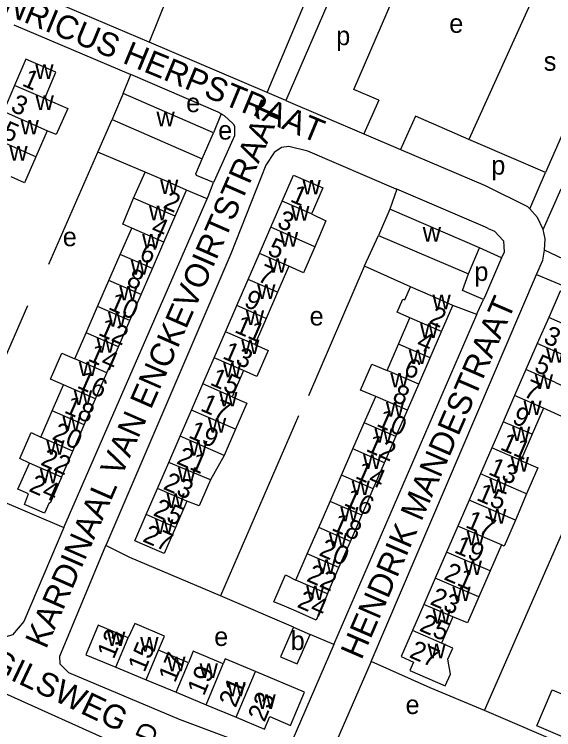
# Model space of a CAD drawing. Extents: x 162804 to 165059, y 381530 to 382901.
# Drawn here: x 163529.9 to 163644.1, y 381809.3 to 381960.8 of the extents above; entities that cross this region are included whole.
import ezdxf

# ---------------------------------------------------------------- set-up
doc = ezdxf.new("R2010")
doc.units = 0
for name, color, linetype in [('BLT_Basislijn', 7, 'Continuous'), ('BLT_Bebouwing', 7, 'Continuous'), ('BLT_Centroide', 7, 'Continuous'), ('BLT_Huisnummer', 7, 'Continuous'), ('BLT_Huisnummer_ tussenligend', 7, 'Continuous'), ('BLT_Onderverdeling_panden', 7, 'Continuous'), ('BLT_Straatnaam', 7, 'Continuous'), ('BLT_Straatnaam_verkleind', 7, 'Continuous')]:
    doc.layers.add(name, color=color, linetype=linetype)

msp = doc.modelspace()

# ---------------------------------------------------------------- linework, layer by layer
at = {"layer": 'BLT_Basislijn'}
for p, q in [((163583.47, 381944.21), (163604.25, 381993.64)), ((163564.81, 381970.7), (163558.49, 381954.86)), ((163643.05, 381971.55), (163626.16, 381934.28)), ((163529.87, 381958.54), (163554.61, 381948.03)), ((163583.47, 381944.21), (163558.49, 381954.86)), ((163553, 381943.96), (163554.61, 381948.03)), ((163650.53, 381946.02), (163642.4, 381927.25)), ((163587.41, 381942.48), (163583.47, 381944.21)), ((163587.41, 381942.48), (163603.92, 381935.46)), ((163607.08, 381942.55), (163603.92, 381935.46)), ((163573.75, 381939.66), (163572.1, 381935.63)), ((163614.86, 381939.18), (163611.68, 381932.16)), ((163622.11, 381936.04), (163614.86, 381939.18)), ((163547.65, 381931.6), (163550.62, 381938.48)), ((163626.16, 381934.28), (163622.11, 381936.04)), ((163603.92, 381935.46), (163611.68, 381932.16)), ((163637.17, 381929.52), (163626.16, 381934.28)), ((163537.22, 381907.84), (163547.65, 381931.6)), ((163557.61, 381927.35), (163547.65, 381931.6)), ((163642.4, 381927.25), (163637.17, 381929.52)), ((163639.05, 381919.56), (163642.4, 381927.25)), ((163570.74, 381921.68), (163566.39, 381923.52)), ((163610.9, 381923.7), (163609.39, 381919.47)), ((163641.88, 381915.19), (163645.68, 381923.83)), ((163540.41, 381852.1), (163570.74, 381921.68)), ((163633.08, 381909.22), (163628.42, 381911.3)), ((163592.25, 381880.07), (163604.04, 381907.4)), ((163613.77, 381903.03), (163604.04, 381907.4)), ((163605.48, 381823.75), (163640.46, 381905.63)), ((163640.46, 381905.63), (163646.54, 381903.09)), ((163532.73, 381899.02), (163516.61, 381862.19)), ((163627.8, 381897.16), (163622.78, 381899.11)), ((163597.55, 381827.29), (163627.8, 381897.16)), ((163629.47, 381813.33), (163659.78, 381882.71)), ((163590.12, 381875.77), (163573.56, 381837.61)), ((163516.61, 381862.19), (163540.41, 381852.1)), ((163589.02, 381830.96), (163573.56, 381837.61)), ((163597.55, 381827.29), (163592.54, 381829.44)), ((163553.38, 381805.49), (163514.14, 381823.1)), ((163653.55, 381803.05), (163629.47, 381813.33))]:
    msp.add_line(p, q, dxfattribs=at)
for points in [[(163558.49, 381954.86), (163523.49, 381969.76), (163513.52, 381972.17), (163497.69, 381979.1), (163495.7, 381979.97)], [(163610.67, 381965.27), (163599.23, 381969.98), (163587.41, 381942.48)], [(163607.08, 381942.55), (163601.81, 381944.83), (163609.95, 381963.6)], [(163573.75, 381939.66), (163573.06, 381940), (163554.61, 381948.03)], [(163573.75, 381939.66), (163574.39, 381939.33), (163576.23, 381937.58), (163576.53, 381937.09), (163576.58, 381935.04), (163572.49, 381926.04), (163572.13, 381925.13)], [(163610.9, 381923.7), (163610.79, 381923.74), (163592.09, 381931.76), (163588.05, 381932.8), (163586.48, 381932.52), (163584.92, 381931.48), (163583.18, 381928.83), (163575.79, 381910.04), (163549.28, 381848.27)], [(163611.68, 381932.16), (163629.61, 381924.53), (163638.58, 381920.07)], [(163572.13, 381925.13), (163568.51, 381926.63), (163568.35, 381926.96), (163569.71, 381930.16)], [(163570.74, 381921.68), (163570.96, 381922.2), (163572.13, 381925.13)], [(163630.26, 381915.42), (163629.69, 381915.67), (163610.9, 381923.7)], [(163639.05, 381919.56), (163638.58, 381920.07)], [(163641.88, 381915.19), (163640.71, 381917.75), (163639.05, 381919.56)], [(163630.26, 381915.42), (163631.54, 381914.84), (163633.47, 381912.77), (163633.6, 381910.42), (163633.08, 381909.22)], [(163642.18, 381910.81), (163642.27, 381913.24), (163641.88, 381915.19)], [(163604.04, 381907.4), (163604.09, 381907.52), (163607.02, 381913.95)], [(163640.46, 381905.63), (163641.77, 381908.72), (163642.18, 381910.81)], [(163690.48, 381889.85), (163648.86, 381907.67), (163642.18, 381910.81)], [(163633.08, 381909.22), (163629.65, 381901.31), (163629.24, 381900.39)], [(163629.24, 381900.39), (163624.78, 381902.26), (163626.05, 381905.77)], [(163627.8, 381897.16), (163628.01, 381897.63), (163629.24, 381900.39)], [(163540.41, 381852.1), (163531.99, 381832.17), (163529.54, 381829.36), (163528.01, 381828.87), (163525.62, 381828.73), (163483.29, 381849.03)], [(163597.55, 381827.29), (163588.69, 381806.75), (163587.02, 381805), (163585.93, 381804.58), (163583.75, 381804.36), (163564.87, 381811.42), (163541.46, 381821.29), (163539.68, 381823.17), (163539.55, 381824.83), (163549.28, 381848.27)], [(163573.56, 381837.61), (163554.4, 381845.76), (163549.28, 381848.27)], [(163605.48, 381823.75), (163598.15, 381806.85), (163597.24, 381803.85), (163596.76, 381800.38), (163598.72, 381798.05), (163642.29, 381783.55), (163644.18, 381783.63), (163645.81, 381785.02), (163653.55, 381803.05)], [(163629.47, 381813.33), (163617.95, 381818.13), (163605.48, 381823.75)]]:
    msp.add_lwpolyline(points, dxfattribs=at)
at = {"layer": 'BLT_Bebouwing'}
for p, q in [((163530.01, 381945.7), (163527.63, 381940.17)), ((163572.1, 381935.63), (163553, 381943.96)), ((163550.62, 381938.48), (163569.71, 381930.16)), ((163536.91, 381936.11), (163534.51, 381930.59)), ((163569.71, 381930.16), (163572.1, 381935.63)), ((163555.2, 381921.83), (163557.61, 381927.35)), ((163563.99, 381918), (163566.39, 381923.52)), ((163584.23, 381915.67), (163586.63, 381921.21)), ((163609.39, 381919.47), (163607.02, 381913.95)), ((163628.42, 381911.3), (163609.39, 381919.47)), ((163561.58, 381912.48), (163563.99, 381918)), ((163552.38, 381909.91), (163554.78, 381915.44)), ((163581.83, 381910.14), (163584.23, 381915.67)), ((163607.02, 381913.95), (163626.05, 381905.77)), ((163559.17, 381906.95), (163561.58, 381912.48)), ((163626.05, 381905.77), (163628.42, 381911.3)), ((163549.97, 381904.39), (163552.38, 381909.91)), ((163579.43, 381904.61), (163581.83, 381910.14)), ((163556.77, 381901.43), (163559.17, 381906.95)), ((163588.04, 381907.45), (163585.64, 381901.91)), ((163547.56, 381898.86), (163549.97, 381904.39)), ((163577.03, 381899.08), (163579.43, 381904.61)), ((163554.36, 381895.9), (163556.77, 381901.43)), ((163585.64, 381901.91), (163583.24, 381896.38)), ((163545.16, 381893.34), (163547.56, 381898.86)), ((163574.63, 381893.54), (163577.03, 381899.08)), ((163620.37, 381893.57), (163622.78, 381899.11)), ((163583.24, 381896.38), (163580.85, 381890.85)), ((163611.26, 381890.93), (163613.67, 381896.48)), ((163643.04, 381896.58), (163640.64, 381891.06)), ((163551.96, 381890.38), (163554.36, 381895.9)), ((163542.75, 381887.81), (163545.16, 381893.34)), ((163572.23, 381888.01), (163574.63, 381893.54)), ((163617.96, 381888.01), (163620.37, 381893.57)), ((163549.55, 381884.85), (163551.96, 381890.38)), ((163608.84, 381885.37), (163611.26, 381890.93)), ((163640.64, 381891.06), (163638.24, 381885.53)), ((163569.83, 381882.48), (163572.23, 381888.01)), ((163615.54, 381882.46), (163617.96, 381888.01)), ((163638.24, 381885.53), (163635.83, 381880.01)), ((163547.14, 381879.33), (163549.55, 381884.85)), ((163578.45, 381885.32), (163576.05, 381879.79)), ((163537.94, 381876.76), (163540.35, 381882.29)), ((163567.43, 381876.95), (163569.83, 381882.48)), ((163613.13, 381876.91), (163615.54, 381882.46)), ((163604.02, 381874.27), (163606.43, 381879.82)), ((163635.83, 381880.01), (163633.43, 381874.48)), ((163544.74, 381873.8), (163547.14, 381879.33)), ((163535.53, 381871.24), (163537.94, 381876.76)), ((163565.04, 381871.42), (163567.43, 381876.95)), ((163610.72, 381871.36), (163613.13, 381876.91)), ((163641.95, 381877.35), (163639.55, 381871.82)), ((163542.33, 381868.28), (163544.74, 381873.8)), ((163601.6, 381868.72), (163604.02, 381874.27)), ((163633.43, 381874.48), (163631.02, 381868.96)), ((163576.79, 381872.94), (163574.37, 381867.36)), ((163562.64, 381865.88), (163565.04, 381871.42)), ((163608.3, 381865.81), (163610.72, 381871.36)), ((163639.55, 381871.82), (163637.15, 381866.29)), ((163631.02, 381868.96), (163628.62, 381863.43)), ((163539.93, 381862.75), (163542.33, 381868.28)), ((163574.37, 381867.36), (163571.45, 381862.16)), ((163599.19, 381863.17), (163601.6, 381868.72)), ((163560.24, 381860.35), (163562.64, 381865.88)), ((163605.89, 381860.25), (163608.3, 381865.81)), ((163596.78, 381857.61), (163599.19, 381863.17)), ((163628.62, 381863.43), (163626.22, 381857.9)), ((163557.84, 381854.82), (163560.24, 381860.35)), ((163603.48, 381854.7), (163605.89, 381860.25)), ((163638.38, 381859.19), (163636.02, 381853.66)), ((163566.45, 381857.66), (163564.05, 381852.12)), ((163594.36, 381852.06), (163596.78, 381857.61)), ((163626.22, 381857.9), (163623.81, 381852.38)), ((163601.07, 381849.15), (163603.48, 381854.7)), ((163623.81, 381852.38), (163621.41, 381846.85)), ((163591.95, 381846.51), (163594.36, 381852.06)), ((163598.65, 381843.6), (163601.07, 381849.15)), ((163633.07, 381848.4), (163630.68, 381842.89)), ((163589.54, 381840.96), (163591.95, 381846.51)), ((163621.41, 381846.85), (163619.01, 381841.33)), ((163596.24, 381838.05), (163598.65, 381843.6)), ((163630.68, 381842.89), (163628.29, 381837.39)), ((163619.01, 381841.33), (163616.6, 381835.8)), ((163616.6, 381835.8), (163614.2, 381830.28)), ((163622.73, 381833.14), (163620.33, 381827.61)), ((163589.02, 381830.96), (163586.31, 381824.74)), ((163566.8, 381823.46), (163560.43, 381826.11)), ((163586.31, 381824.74), (163589.83, 381823.21)), ((163551.46, 381822.51), (163557.82, 381819.85)), ((163557.82, 381819.85), (163564.19, 381817.2)), ((163564.19, 381817.2), (163570.55, 381814.55)), ((163570.55, 381814.55), (163576.92, 381811.9))]:
    msp.add_line(p, q, dxfattribs=at)
for points in [[(163536.39, 381942.96), (163536.67, 381943.62), (163538.76, 381948.49), (163532.39, 381951.23), (163530.01, 381945.7)], [(163553, 381943.96), (163550.92, 381939.2), (163550.62, 381938.48)], [(163536.39, 381942.96), (163541.26, 381940.84), (163538.8, 381935.31), (163536.91, 381936.11)], [(163534.51, 381930.59), (163532.12, 381925.09), (163529.26, 381926.37)], [(163566.39, 381923.52), (163562.26, 381925.32), (163557.61, 381927.35)], [(163586.63, 381921.21), (163589.03, 381926.73), (163595.24, 381924.04), (163593.25, 381919.45), (163592.84, 381918.51)], [(163554.78, 381915.44), (163552.89, 381916.3), (163555.2, 381921.83)], [(163592.84, 381918.51), (163595.91, 381917.01), (163593.52, 381911.5)], [(163593.52, 381911.5), (163591.13, 381905.99), (163588.04, 381907.45)], [(163613.67, 381896.48), (163610.95, 381897.71), (163612.16, 381900.46), (163612.58, 381900.28), (163613.77, 381903.03)], [(163622.78, 381899.11), (163618.49, 381900.98), (163613.77, 381903.03)], [(163646.54, 381903.09), (163646.01, 381901.86), (163645.44, 381902.11), (163643.04, 381896.58)], [(163580.85, 381890.85), (163583.66, 381889.6), (163581.27, 381884.09), (163578.45, 381885.32)], [(163540.35, 381882.29), (163537.6, 381883.49), (163540, 381889.01), (163542.75, 381887.81)], [(163606.43, 381879.82), (163603.19, 381881.18), (163605.59, 381886.7), (163608.84, 381885.37)], [(163644.36, 381882.87), (163648.21, 381881.06), (163645.82, 381875.56), (163641.95, 381877.35)], [(163576.05, 381879.79), (163579.18, 381878.45), (163576.79, 381872.94)], [(163533.13, 381865.71), (163531.11, 381866.72), (163533.5, 381872.22), (163535.53, 381871.24)], [(163637.15, 381866.29), (163640.76, 381864.69), (163638.38, 381859.19)], [(163539.93, 381862.75), (163537.52, 381857.23), (163537.3, 381857.32), (163536.34, 381855.12), (163532.09, 381856.97), (163532.94, 381859.22), (163530.72, 381860.19), (163533.13, 381865.71)], [(163571.45, 381862.16), (163569.06, 381856.66), (163566.45, 381857.66)], [(163564.05, 381852.12), (163561.65, 381846.59), (163559.71, 381847.43), (163555.44, 381849.29), (163557.84, 381854.82)], [(163636.02, 381853.66), (163633.62, 381848.16), (163633.07, 381848.4)], [(163596.24, 381838.05), (163593.83, 381832.49), (163589.59, 381834.34), (163587.12, 381835.41), (163584.86, 381836.35), (163587.36, 381842.1), (163589.54, 381840.96)], [(163628.29, 381837.39), (163625.89, 381831.89), (163622.73, 381833.14)], [(163554.07, 381828.76), (163547.7, 381831.42), (163545.1, 381825.16), (163551.46, 381822.51)], [(163560.43, 381826.11), (163561.74, 381829.11), (163555.43, 381831.74), (163554.07, 381828.76)], [(163589.02, 381830.96), (163592.54, 381829.44)], [(163614.2, 381830.28), (163611.8, 381824.75), (163614.46, 381823.59), (163613.67, 381821.79), (163621.15, 381818.53), (163622.23, 381821.01), (163621.72, 381824.24), (163622.73, 381826.57), (163620.33, 381827.61)], [(163589.83, 381823.21), (163592.54, 381829.44)], [(163574.17, 381823.24), (163567.81, 381825.89), (163566.8, 381823.46)], [(163580.96, 381821.61), (163574.56, 381824.28), (163574.17, 381823.24)], [(163576.92, 381811.9), (163582.92, 381809.39), (163584.02, 381812.05), (163588.42, 381810.2), (163591.38, 381817.25), (163580.96, 381821.61)], [(163652.76, 381813.71), (163650.3, 381808.02), (163649.45, 381806.26), (163640.52, 381810.11), (163643.79, 381817.7), (163646.09, 381816.71)]]:
    msp.add_lwpolyline(points, dxfattribs=at)
at = {"layer": 'BLT_Onderverdeling_panden'}
for p, q in [((163536.39, 381942.96), (163530.01, 381945.7)), ((163536.91, 381936.11), (163527.63, 381940.17)), ((163534.51, 381930.59), (163525.25, 381934.64)), ((163563.99, 381918), (163555.2, 381921.83)), ((163592.84, 381918.51), (163586.63, 381921.21)), ((163561.58, 381912.48), (163554.78, 381915.44)), ((163593.52, 381911.5), (163584.23, 381915.67)), ((163559.17, 381906.95), (163552.38, 381909.91)), ((163588.04, 381907.45), (163581.83, 381910.14)), ((163556.77, 381901.43), (163549.97, 381904.39)), ((163585.64, 381901.91), (163579.43, 381904.61)), ((163554.36, 381895.9), (163547.56, 381898.86)), ((163583.24, 381896.38), (163577.03, 381899.08)), ((163620.37, 381893.57), (163613.67, 381896.48)), ((163652.74, 381892.22), (163643.04, 381896.58)), ((163551.96, 381890.38), (163545.16, 381893.34)), ((163580.85, 381890.85), (163574.63, 381893.54)), ((163617.96, 381888.01), (163611.26, 381890.93)), ((163646.76, 381888.4), (163640.64, 381891.06)), ((163549.55, 381884.85), (163542.75, 381887.81)), ((163578.45, 381885.32), (163572.23, 381888.01)), ((163644.36, 381882.87), (163638.24, 381885.53)), ((163615.54, 381882.46), (163608.84, 381885.37)), ((163547.14, 381879.33), (163540.35, 381882.29)), ((163576.05, 381879.79), (163569.83, 381882.48)), ((163613.13, 381876.91), (163606.43, 381879.82)), ((163641.95, 381877.35), (163635.83, 381880.01)), ((163544.74, 381873.8), (163537.94, 381876.76)), ((163576.79, 381872.94), (163567.43, 381876.95)), ((163610.72, 381871.36), (163604.02, 381874.27)), ((163639.55, 381871.82), (163633.43, 381874.48)), ((163542.33, 381868.28), (163535.53, 381871.24)), ((163574.37, 381867.36), (163565.04, 381871.42)), ((163637.15, 381866.29), (163631.02, 381868.96)), ((163608.3, 381865.81), (163601.6, 381868.72)), ((163571.45, 381862.16), (163562.64, 381865.88)), ((163539.93, 381862.75), (163533.13, 381865.71)), ((163605.89, 381860.25), (163599.19, 381863.17)), ((163638.38, 381859.19), (163628.62, 381863.43)), ((163566.45, 381857.66), (163560.24, 381860.35)), ((163603.48, 381854.7), (163596.78, 381857.61)), ((163636.02, 381853.66), (163626.22, 381857.9)), ((163564.05, 381852.12), (163557.84, 381854.82)), ((163633.07, 381848.4), (163623.81, 381852.38)), ((163601.07, 381849.15), (163594.36, 381852.06)), ((163598.65, 381843.6), (163591.95, 381846.51)), ((163630.68, 381842.89), (163621.41, 381846.85)), ((163596.24, 381838.05), (163589.54, 381840.96)), ((163628.29, 381837.39), (163619.01, 381841.33)), ((163622.73, 381833.14), (163616.6, 381835.8)), ((163620.33, 381827.61), (163614.2, 381830.28)), ((163551.46, 381822.51), (163554.07, 381828.76)), ((163557.82, 381819.85), (163560.43, 381826.11)), ((163564.19, 381817.2), (163566.8, 381823.46)), ((163570.55, 381814.55), (163574.17, 381823.24)), ((163576.92, 381811.9), (163580.96, 381821.61))]:
    msp.add_line(p, q, dxfattribs=at)

# ---------------------------------------------------------------- texts
at = {"layer": 'BLT_Centroide'}
for s, p in [('e', (163622, 381956.84)), ('p', (163598.07, 381954.22)), ('s', (163642, 381948.81)), ('w', (163534.38, 381947.09)), ('w', (163534.44, 381940.5)), ('e', (163566.32, 381940.04)), ('w', (163560.03, 381937.06)), ('w', (163531.27, 381935.31)), ('e', (163573.09, 381934.23)), ('w', (163528.89, 381929.78)), ('p', (163630.9, 381926.81)), ('w', (163560.79, 381922.69)), ('w', (163590.94, 381922.62)), ('w', (163558.43, 381917.16)), ('w', (163588.54, 381917.09)), ('e', (163540.2, 381911.65)), ('w', (163586.14, 381911.56)), ('w', (163616.38, 381912.62)), ('w', (163556.98, 381911.19)), ('w', (163554.57, 381905.66)), ('w', (163583.73, 381906.03)), ('p', (163627.31, 381904.3)), ('w', (163552.16, 381900.16)), ('w', (163581.34, 381900.5)), ('w', (163618.44, 381898.31)), ('w', (163549.76, 381894.62)), ('w', (163578.94, 381894.97)), ('e', (163592.44, 381894.87)), ('w', (163615.81, 381892.25)), ('w', (163547.35, 381889.09)), ('w', (163577.95, 381888.81)), ('w', (163613.41, 381886.69)), ('w', (163642.5, 381886.97)), ('w', (163543.57, 381884.16)), ('w', (163574.14, 381883.91)), ('w', (163609.52, 381881.75)), ('w', (163640.09, 381881.44)), ('w', (163542.54, 381878.03)), ('w', (163573.31, 381877.72)), ('w', (163608.58, 381875.59)), ('w', (163637.69, 381875.91)), ('w', (163540.13, 381872.53)), ('w', (163570.92, 381872.19)), ('w', (163635.28, 381870.38)), ('w', (163606.16, 381870.03)), ('w', (163536.71, 381867.5)), ('w', (163566.94, 381867.31)), ('w', (163603.75, 381864.5)), ('w', (163635.02, 381863.94)), ('w', (163535.33, 381861.47)), ('w', (163564.54, 381861.78)), ('w', (163601.33, 381858.94)), ('w', (163630.48, 381859.34)), ('w', (163562.14, 381856.25)), ('w', (163598.92, 381853.38)), ('w', (163630.23, 381852.91)), ('w', (163559.74, 381850.72)), ('w', (163596.51, 381847.84)), ('w', (163625.67, 381848.28)), ('w', (163594.09, 381842.28)), ('w', (163625.06, 381842.03)), ('w', (163591.69, 381836.72)), ('w', (163622.66, 381836.5)), ('w', (163618.47, 381831.72)), ('w', (163549.58, 381826.97)), ('e', (163572.25, 381827.01)), ('b', (163588.43, 381826.14)), ('w', (163556.59, 381825.81)), ('w', (163617.39, 381824.41)), ('w', (163562.31, 381821.66)), ('w', (163569.16, 381820.23)), ('w', (163575.03, 381816.34)), ('w', (163581.41, 381813.69)), ('e', (163612.75, 381812.59))]:
    msp.add_text(s, height=4, dxfattribs=at).set_placement(p)
at = {"layer": 'BLT_Huisnummer'}
for s, rotation, p in [('1', 336.7537, (163531.37, 381945.73)), ('5', 336.7538, (163527.05, 381934.65)), ('1', 336.7537, (163588.13, 381921.2)), ('2', 336.4706, (163561.23, 381919.85)), ('5', 336.7538, (163583.31, 381909.95)), ('6', 336.4706, (163556.17, 381908.93)), ('9', 336.7615, (163578.34, 381898.98)), ('10', 336.4706, (163549.64, 381898.39)), ('2', 336.4706, (163617.49, 381895.48)), ('14', 336.4706, (163545.3, 381887.49)), ('13', 336.7541, (163573.81, 381887.97)), ('5', 336.7538, (163639.74, 381885.25)), ('6', 336.4706, (163612.1, 381884.56)), ('18', 336.4706, (163540.29, 381876.49)), ('17', 336.7509, (163569.12, 381876.93)), ('10', 336.4706, (163606.4, 381873.68)), ('9', 336.7615, (163635.1, 381874.28)), ('21', 336.7585, (163564.07, 381865.7)), ('13', 336.7541, (163630.07, 381863.43)), ('14', 336.4706, (163601.9, 381862.62)), ('24', 336.4704, (163532.82, 381859.86)), ('17', 336.7509, (163625.21, 381852.22)), ('18', 336.4706, (163596.89, 381851.61)), ('27', 336.5937, (163556.9, 381849.21)), ('21', 336.7585, (163620.66, 381841.17)), ('24', 336.4704, (163589.59, 381835.33)), ('13', 67.3762, (163550.98, 381824.04)), ('27', 336.5937, (163613.32, 381824.68)), ('17', 67.373, (163563.95, 381819.04)), ('23', 67.3749, (163582.89, 381810.71))]:
    msp.add_text(s, height=4, rotation=rotation, dxfattribs=at).set_placement(p)
at = {"layer": 'BLT_Huisnummer_ tussenligend'}
for s, rotation, p in [('3', 336.7537, (163528.95, 381940.33)), ('3', 336.7537, (163585.33, 381915.79)), ('4', 336.4706, (163558.64, 381914.41)), ('8', 336.4706, (163553.46, 381903.48)), ('7', 336.7538, (163581.17, 381904.37)), ('11', 336.7615, (163576.33, 381893.52)), ('12', 336.4706, (163547.5, 381892.94)), ('3', 336.7537, (163641.72, 381891.3)), ('4', 336.4706, (163614.82, 381890.17)), ('15', 336.7541, (163571.15, 381882.39)), ('16', 336.4706, (163543.02, 381881.76)), ('7', 336.7538, (163637.47, 381879.94)), ('8', 336.4706, (163609.72, 381878.98)), ('20', 336.4706, (163537.73, 381870.87)), ('19', 336.7509, (163566.6, 381871.21)), ('12', 336.4706, (163604.16, 381868.36)), ('11', 336.7615, (163632.57, 381868.68)), ('22', 336.4706, (163535.31, 381865.43)), ('23', 336.7585, (163561.26, 381860.3)), ('16', 336.4706, (163599.51, 381856.9)), ('15', 336.7541, (163627.55, 381857.98)), ('25', 336.7585, (163559.14, 381854.72)), ('20', 336.4706, (163594.22, 381846.28)), ('19', 336.7509, (163622.83, 381846.9)), ('22', 336.4706, (163591.58, 381840.83)), ('23', 336.7585, (163617.73, 381835.9)), ('25', 336.7585, (163615.47, 381830.31)), ('15', 67.3762, (163557.49, 381821.25)), ('19', 67.373, (163570.06, 381816.26)), ('21', 67.373, (163576.76, 381813.76))]:
    msp.add_text(s, height=4, rotation=rotation, dxfattribs=at).set_placement(p)
at = {"layer": 'BLT_Straatnaam'}
for s, height, rotation, p in [('HENRICUS HERPSTRAAT', 5, 337.5512, (163518.65, 381964.6)), ('KARDINAAL VAN ENCKEVOIRTSTRAAT', 4.9999, 66.3764, (163536.65, 381826.19)), ('HENDRIK MANDESTRAAT', 5, 66.6116, (163603.41, 381823.88)), ('ANTONIUS VAN GILSWEG', 5, 334.5611, (163477.26, 381844.48)), ('VAN RENESSEWEG', 5, 67.4162, (163641.8, 381756.22))]:
    msp.add_text(s, height=height, rotation=rotation, dxfattribs=at).set_placement(p)
at = {"layer": 'BLT_Straatnaam_verkleind'}
msp.add_text('ST PLECHELMUSPAD', height=4, rotation=66.8957, dxfattribs=at).set_placement((163538.81, 381758.62))

doc.saveas('drawing.dxf')
